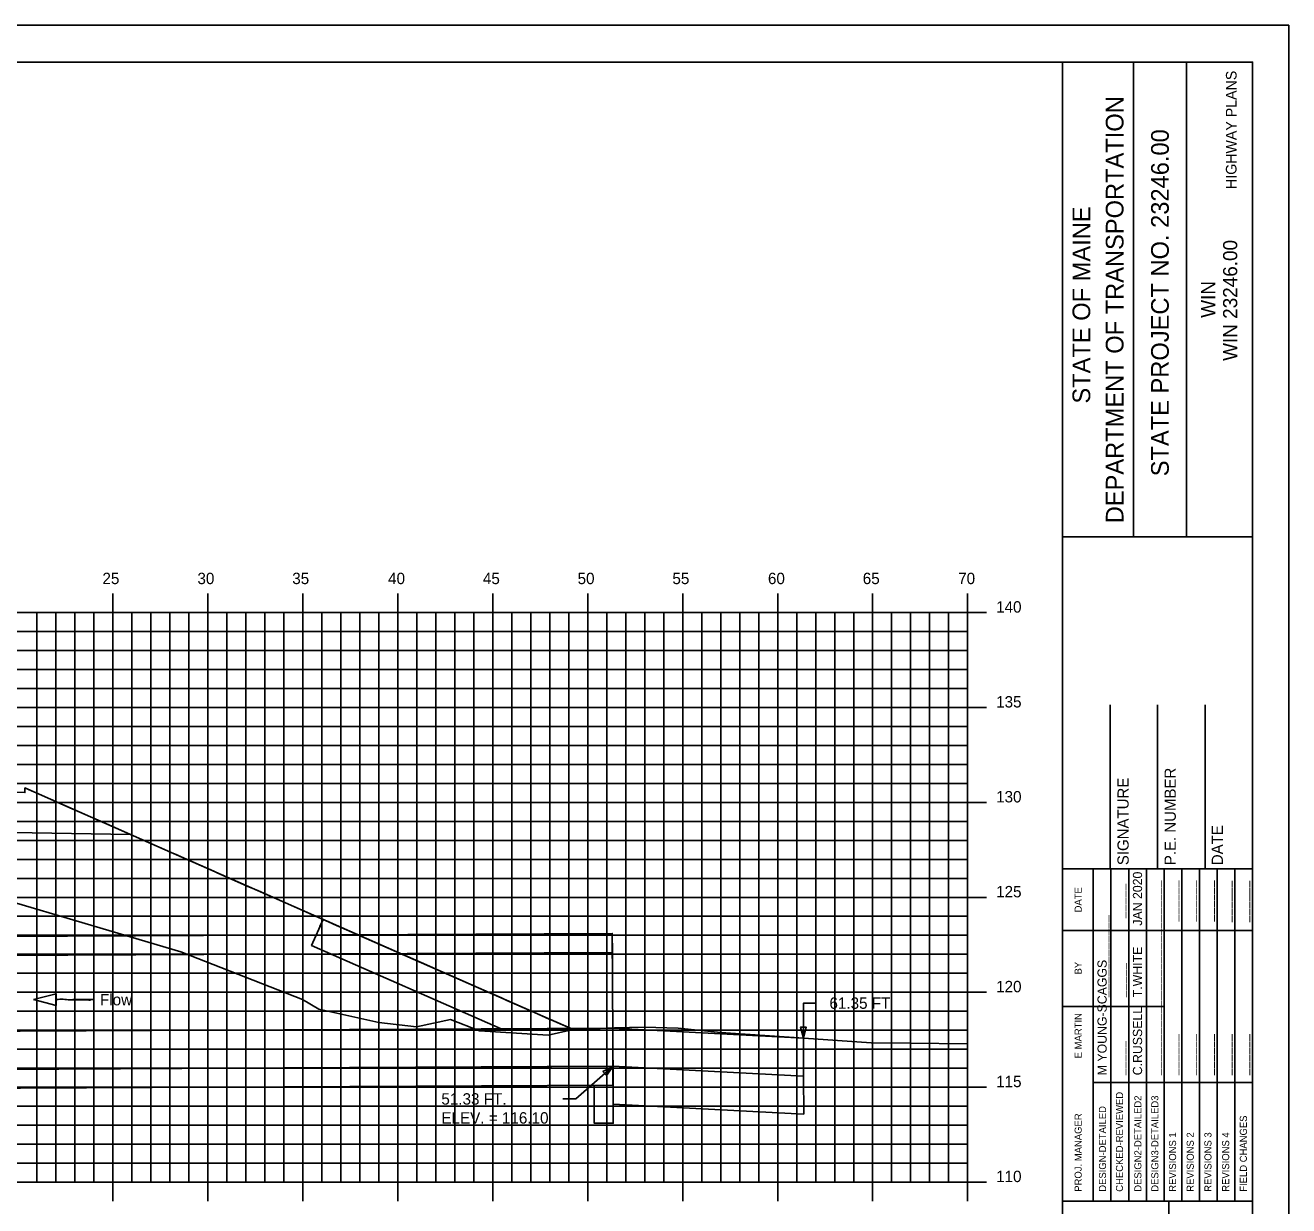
# Model space of a CAD drawing. Extents: x 1145859 to 1146029, y 608981 to 609091.
# Drawn here: x 1145962.8 to 1146029.3, y 609029.1 to 609091.3 of the extents above; entities that cross this region are included whole.
import ezdxf

# ---------------------------------------------------------------- set-up
doc = ezdxf.new("R2010")
doc.units = 0
for name, color, linetype in [('BORDER', 7, 'Continuous'), ('D_Drainage_Culvert', 7, 'Continuous'), ('D_Roadway_SlopeLines', 7, 'Continuous'), ('D_Roadway_SubGrade', 7, 'Continuous'), ('D_Text_Standard', 7, 'Continuous'), ('H_V ANNOTATION', 7, 'Continuous'), ('HIGHWAY_TITLE', 7, 'Continuous'), ('MAJOR', 7, 'Continuous'), ('MINOR', 7, 'Continuous'), ('PATTERNING', 7, 'Continuous'), ('PLOT BOUNDARY', 7, 'Continuous'), ('S_Roadway_Centerline', 7, 'Continuous'), ('WATER_DAM', 7, 'Continuous')]:
    doc.layers.add(name, color=color, linetype=linetype)

msp = doc.modelspace()

# ---------------------------------------------------------------- linework, layer by layer
msp.add_lwpolyline([(1145962.768, 609051.1), (1145963.118, 609050.946), (1145963.237, 609050.893), (1145963.479, 609050.786), (1145965.131, 609050.057), (1145965.943, 609049.698), (1145967.025, 609049.221), (1145968.331, 609048.645), (1145968.918, 609048.386), (1145968.972, 609048.362), (1145968.994, 609048.352), (1145969.706, 609048.038), (1145970.593, 609047.647), (1145970.812, 609047.55), (1145970.835, 609047.54), (1145972.706, 609046.715), (1145972.929, 609046.616), (1145974.599, 609045.879), (1145975.022, 609045.693), (1145976.493, 609045.044), (1145977.707, 609044.509), (1145978.387, 609044.209), (1145978.76, 609044.044), (1145979.019, 609043.93), (1145979.704, 609043.628), (1145980.28, 609043.374), (1145981.174, 609042.98), (1145982.174, 609042.539), (1145982.909, 609042.215), (1145984.068, 609041.704), (1145984.65, 609041.447), (1145985.962, 609040.869), (1145986.395, 609040.678), (1145987.855, 609040.035), (1145988.142, 609039.908), (1145989.749, 609039.2), (1145989.798, 609039.178), (1145990.37, 609038.926), (1145990.436, 609038.897), (1145991.643, 609038.366), (1145991.643, 609038.365), (1145991.651, 609038.362)])
at = {"layer": 'BORDER'}
for p, q in [((1146017.402, 608984.335), (1146017.402, 609089.335)), ((1146021.13, 609064.332), (1146021.13, 609089.332)), ((1146023.925, 609064.332), (1146023.925, 609089.332)), ((1146017.403, 609064.329), (1146027.402, 609064.329)), ((1146019.902, 609046.838), (1146019.902, 609055.485)), ((1146022.402, 609046.838), (1146022.402, 609055.485)), ((1146024.902, 609046.838), (1146024.902, 609055.485)), ((1146017.402, 609046.838), (1146027.402, 609046.838)), ((1146017.402, 609029.338), (1146027.402, 609029.338)), ((1146022.993, 608994.338), (1146022.993, 609029.338))]:
    msp.add_line(p, q, dxfattribs=at)
msp.add_lwpolyline([(1145867.402, 608984.335), (1146027.402, 608984.335), (1146027.402, 609089.335), (1145867.402, 609089.335)], close=True, dxfattribs=at)
for points in [[(1146019.017, 609043.588), (1146019.017, 609046.838)], [(1146019.949, 609029.341), (1146019.949, 609046.838)], [(1146020.881, 609046.838), (1146020.881, 609029.341)], [(1146021.813, 609029.341), (1146021.813, 609046.838)], [(1146022.744, 609029.341), (1146022.744, 609046.838)], [(1146023.676, 609029.341), (1146023.676, 609046.838)], [(1146024.608, 609029.341), (1146024.608, 609046.838)], [(1146025.539, 609029.341), (1146025.539, 609046.838)], [(1146026.471, 609029.341), (1146026.471, 609046.838)], [(1146019.018, 609029.341), (1146019.018, 609046.132)], [(1146017.402, 609043.588), (1146027.402, 609043.588)], [(1146017.402, 609039.588), (1146019.018, 609039.588)], [(1146019.017, 609039.588), (1146022.743, 609039.588)], [(1146019.017, 609035.588), (1146027.402, 609035.588)]]:
    msp.add_lwpolyline(points, dxfattribs=at)
at = {"layer": 'D_Drainage_Culvert'}
for points in [[(1145889.737, 609034.915), (1145993.735, 609035.435), (1145993.695, 609043.435), (1145889.697, 609042.915)], [(1145889.732, 609035.915), (1145993.73, 609036.435), (1145993.7, 609042.435), (1145889.702, 609041.915)], [(1145993.735, 609035.435), (1145992.735, 609035.43), (1145992.745, 609033.43), (1145993.745, 609033.435)]]:
    msp.add_lwpolyline(points, close=True, dxfattribs=at)
at = {"layer": 'D_Roadway_SlopeLines'}
for points in [[(1145968.331, 609048.645), (1145970.594, 609047.647)], [(1145970.594, 609047.647), (1145991.511, 609038.424)]]:
    msp.add_lwpolyline(points, dxfattribs=at)
at = {"layer": 'D_Roadway_SubGrade'}
msp.add_lwpolyline([(1145954.848, 609050.962), (1145954.848, 609051.129), (1145962.768, 609050.852), (1145962.768, 609051.102), (1145962.768, 609051.102), (1145968.331, 609048.645), (1145954.848, 609048.879)], close=True, dxfattribs=at)
at = {"layer": 'D_Text_Standard'}
for points in [[(1146003.752, 609037.912), (1146003.766, 609039.762), (1146004.446, 609039.762)], [(1145993.732, 609036.435), (1145991.777, 609034.716), (1145991.097, 609034.716)]]:
    msp.add_lwpolyline(points, dxfattribs=at)
for points in [[(1146003.752, 609037.912), (1146003.611, 609038.496), (1146003.902, 609038.493)], [(1145993.732, 609036.435), (1145993.391, 609035.941), (1145993.198, 609036.16)]]:
    msp.add_lwpolyline(points, close=True, dxfattribs=at)
at = {"layer": 'MAJOR'}
for p, q in [((1145967.402, 609061.337), (1145967.402, 609060.335)), ((1145972.402, 609061.337), (1145972.402, 609060.335)), ((1145977.402, 609061.337), (1145977.402, 609060.335)), ((1145982.402, 609061.337), (1145982.402, 609060.335)), ((1145987.402, 609061.337), (1145987.402, 609060.335)), ((1145992.402, 609061.337), (1145992.402, 609060.335)), ((1145997.402, 609061.337), (1145997.402, 609060.335)), ((1146002.402, 609061.337), (1146002.402, 609060.335)), ((1146007.402, 609061.337), (1146007.402, 609060.335)), ((1146012.402, 609061.337), (1146012.402, 609060.335)), ((1145872.402, 609060.335), (1146012.402, 609060.335)), ((1145872.402, 609060.335), (1146012.402, 609060.335)), ((1145967.402, 609030.335), (1145967.402, 609060.335)), ((1145972.402, 609030.335), (1145972.402, 609060.335)), ((1145977.402, 609030.335), (1145977.402, 609060.335)), ((1145982.402, 609030.335), (1145982.402, 609060.335)), ((1145987.402, 609030.335), (1145987.402, 609060.335)), ((1145992.402, 609030.335), (1145992.402, 609060.335)), ((1145997.402, 609030.335), (1145997.402, 609060.335)), ((1146002.402, 609030.335), (1146002.402, 609060.335)), ((1146007.402, 609030.335), (1146007.402, 609060.335)), ((1146013.404, 609060.335), (1146011.4, 609060.335)), ((1146012.402, 609030.335), (1146012.402, 609060.335)), ((1146012.402, 609030.335), (1146012.402, 609060.335)), ((1145872.402, 609055.335), (1146012.402, 609055.335)), ((1146013.404, 609055.335), (1146011.4, 609055.335)), ((1145872.402, 609050.335), (1146012.402, 609050.335)), ((1146013.404, 609050.335), (1146011.4, 609050.335)), ((1145872.402, 609045.335), (1146012.402, 609045.335)), ((1146013.404, 609045.335), (1146011.4, 609045.335)), ((1145872.402, 609040.335), (1146012.402, 609040.335)), ((1146013.404, 609040.335), (1146011.4, 609040.335)), ((1145872.402, 609035.335), (1146012.402, 609035.335)), ((1146013.404, 609035.335), (1146011.4, 609035.335)), ((1145872.402, 609030.335), (1146012.402, 609030.335)), ((1145872.402, 609030.335), (1146012.402, 609030.335)), ((1145967.402, 609029.333), (1145967.402, 609030.335)), ((1145972.402, 609029.333), (1145972.402, 609030.335)), ((1145977.402, 609029.333), (1145977.402, 609030.335)), ((1145982.402, 609029.333), (1145982.402, 609030.335)), ((1145987.402, 609029.333), (1145987.402, 609030.335)), ((1145992.402, 609029.333), (1145992.402, 609030.335)), ((1145997.402, 609029.333), (1145997.402, 609030.335)), ((1146002.402, 609029.333), (1146002.402, 609030.335)), ((1146007.402, 609029.333), (1146007.402, 609030.335)), ((1146013.404, 609030.335), (1146011.4, 609030.335)), ((1146012.402, 609029.333), (1146012.402, 609030.335))]:
    msp.add_line(p, q, dxfattribs=at)
at = {"layer": 'MINOR'}
for p, q in [((1145963.402, 609030.335), (1145963.402, 609060.335)), ((1145964.402, 609030.335), (1145964.402, 609060.335)), ((1145965.402, 609030.335), (1145965.402, 609060.335)), ((1145966.402, 609030.335), (1145966.402, 609060.335)), ((1145968.402, 609030.335), (1145968.402, 609060.335)), ((1145969.402, 609030.335), (1145969.402, 609060.335)), ((1145970.402, 609030.335), (1145970.402, 609060.335)), ((1145971.402, 609030.335), (1145971.402, 609060.335)), ((1145973.402, 609030.335), (1145973.402, 609060.335)), ((1145974.402, 609030.335), (1145974.402, 609060.335)), ((1145975.402, 609030.335), (1145975.402, 609060.335)), ((1145976.402, 609030.335), (1145976.402, 609060.335)), ((1145978.402, 609030.335), (1145978.402, 609060.335)), ((1145979.402, 609030.335), (1145979.402, 609060.335)), ((1145980.402, 609030.335), (1145980.402, 609060.335)), ((1145981.402, 609030.335), (1145981.402, 609060.335)), ((1145983.402, 609030.335), (1145983.402, 609060.335)), ((1145984.402, 609030.335), (1145984.402, 609060.335)), ((1145985.402, 609030.335), (1145985.402, 609060.335)), ((1145986.402, 609030.335), (1145986.402, 609060.335)), ((1145988.402, 609030.335), (1145988.402, 609060.335)), ((1145989.402, 609030.335), (1145989.402, 609060.335)), ((1145990.402, 609030.335), (1145990.402, 609060.335)), ((1145991.402, 609030.335), (1145991.402, 609060.335)), ((1145993.402, 609030.335), (1145993.402, 609060.335)), ((1145994.402, 609030.335), (1145994.402, 609060.335)), ((1145995.402, 609030.335), (1145995.402, 609060.335)), ((1145996.402, 609030.335), (1145996.402, 609060.335)), ((1145998.402, 609030.335), (1145998.402, 609060.335)), ((1145999.402, 609030.335), (1145999.402, 609060.335)), ((1146000.402, 609030.335), (1146000.402, 609060.335)), ((1146001.402, 609030.335), (1146001.402, 609060.335)), ((1146003.402, 609030.335), (1146003.402, 609060.335)), ((1146004.402, 609030.335), (1146004.402, 609060.335)), ((1146005.402, 609030.335), (1146005.402, 609060.335)), ((1146006.402, 609030.335), (1146006.402, 609060.335)), ((1146008.402, 609030.335), (1146008.402, 609060.335)), ((1146009.402, 609030.335), (1146009.402, 609060.335)), ((1146010.402, 609030.335), (1146010.402, 609060.335)), ((1146011.402, 609030.335), (1146011.402, 609060.335)), ((1145872.402, 609059.335), (1146012.402, 609059.335)), ((1146012.402, 609059.335), (1146011.4, 609059.335)), ((1145872.402, 609058.335), (1146012.402, 609058.335)), ((1146012.402, 609058.335), (1146011.4, 609058.335)), ((1145872.402, 609057.335), (1146012.402, 609057.335)), ((1146012.402, 609057.335), (1146011.4, 609057.335)), ((1145872.402, 609056.335), (1146012.402, 609056.335)), ((1146012.402, 609056.335), (1146011.4, 609056.335)), ((1145872.402, 609054.335), (1146012.402, 609054.335)), ((1146012.402, 609054.335), (1146011.4, 609054.335)), ((1145872.402, 609053.335), (1146012.402, 609053.335)), ((1146012.402, 609053.335), (1146011.4, 609053.335)), ((1145872.402, 609052.335), (1146012.402, 609052.335)), ((1146012.402, 609052.335), (1146011.4, 609052.335)), ((1145872.402, 609051.335), (1146012.402, 609051.335)), ((1146012.402, 609051.335), (1146011.4, 609051.335)), ((1145872.402, 609049.335), (1146012.402, 609049.335)), ((1146012.402, 609049.335), (1146011.4, 609049.335)), ((1145872.402, 609048.335), (1146012.402, 609048.335)), ((1146012.402, 609048.335), (1146011.4, 609048.335)), ((1145872.402, 609047.335), (1146012.402, 609047.335)), ((1146012.402, 609047.335), (1146011.4, 609047.335)), ((1145872.402, 609046.335), (1146012.402, 609046.335)), ((1146012.402, 609046.335), (1146011.4, 609046.335)), ((1145872.402, 609044.335), (1146012.402, 609044.335)), ((1146012.402, 609044.335), (1146011.4, 609044.335)), ((1145872.402, 609043.335), (1146012.402, 609043.335)), ((1146012.402, 609043.335), (1146011.4, 609043.335)), ((1145872.402, 609042.335), (1146012.402, 609042.335)), ((1146012.402, 609042.335), (1146011.4, 609042.335)), ((1145872.402, 609041.335), (1146012.402, 609041.335)), ((1146012.402, 609041.335), (1146011.4, 609041.335)), ((1145872.402, 609039.335), (1146012.402, 609039.335)), ((1146012.402, 609039.335), (1146011.4, 609039.335)), ((1145872.402, 609038.335), (1146012.402, 609038.335)), ((1146012.402, 609038.335), (1146011.4, 609038.335)), ((1145872.402, 609037.335), (1146012.402, 609037.335)), ((1146012.402, 609037.335), (1146011.4, 609037.335)), ((1145872.402, 609036.335), (1146012.402, 609036.335)), ((1146012.402, 609036.335), (1146011.4, 609036.335)), ((1145872.402, 609034.335), (1146012.402, 609034.335)), ((1146012.402, 609034.335), (1146011.4, 609034.335)), ((1145872.402, 609033.335), (1146012.402, 609033.335)), ((1146012.402, 609033.335), (1146011.4, 609033.335)), ((1145872.402, 609032.335), (1146012.402, 609032.335)), ((1146012.402, 609032.335), (1146011.4, 609032.335)), ((1145872.402, 609031.335), (1146012.402, 609031.335)), ((1146012.402, 609031.335), (1146011.4, 609031.335))]:
    msp.add_line(p, q, dxfattribs=at)
at = {"layer": 'PATTERNING'}
for p, q in [((1145993.7, 609042.435), (1145993.695, 609043.435)), ((1145889.702, 609041.915), (1145993.7, 609042.435)), ((1145991.511, 609038.424), (1145991.511, 609038.424)), ((1145993.73, 609036.435), (1145889.732, 609035.915)), ((1145889.732, 609035.915), (1145993.732, 609036.435))]:
    msp.add_line(p, q, dxfattribs=at)
for points in [[(1145991.511, 609038.424), (1145980.298, 609043.368), (1145978.468, 609044.175), (1145977.863, 609042.802), (1145987.837, 609038.406), (1145991.511, 609038.424)], [(1145980.298, 609043.368), (1145978.468, 609044.175), (1145978.3, 609043.795)], [(1145993.695, 609043.435), (1145889.697, 609042.915), (1145889.702, 609041.915)], [(1145889.737, 609034.915), (1145993.735, 609035.435), (1145993.73, 609036.435)]]:
    msp.add_lwpolyline(points, dxfattribs=at)
for points in [[(1145889.732, 609035.915), (1145889.722, 609037.915), (1145993.72, 609038.435), (1145993.73, 609036.435)], [(1145993.72, 609038.435), (1146003.752, 609037.912), (1146003.761, 609035.912), (1145993.73, 609036.435)], [(1145993.73, 609036.435), (1146003.761, 609035.912), (1146003.771, 609033.913), (1145993.74, 609034.435)]]:
    msp.add_lwpolyline(points, close=True, dxfattribs=at)
at = {"layer": 'PLOT BOUNDARY'}
msp.add_lwpolyline([(1145859.308, 608981.276), (1146029.308, 608981.276), (1146029.308, 609091.276), (1145859.308, 609091.276)], close=True, dxfattribs=at)
at = {"layer": 'S_Roadway_Centerline'}
msp.add_lwpolyline([(1145956.617, 609046.711), (1145970.97, 609042.471), (1145977.379, 609039.948), (1145978.241, 609039.442), (1145981.393, 609038.75), (1145983.393, 609038.522), (1145985.169, 609038.895), (1145986.704, 609038.311), (1145990.311, 609038.078), (1145991.564, 609038.358), (1145993.811, 609038.455), (1145995.381, 609038.499), (1145997.157, 609038.441), (1145999.407, 609038.212), (1146003.773, 609037.911), (1146007.319, 609037.668), (1146009.397, 609037.646), (1146012.402, 609037.617)], dxfattribs=at)
at = {"layer": 'WATER_DAM'}
msp.add_lwpolyline([(1145963.218, 609039.945), (1145964.418, 609040.245), (1145964.418, 609039.645)], close=True, dxfattribs=at)
msp.add_open_spline([(1145964.418, 609039.945), (1145964.668, 609039.995), (1145965.168, 609039.895), (1145965.668, 609039.995), (1145966.168, 609039.895), (1145966.418, 609039.945), (1145964.418, 609039.945), (1145966.418, 609039.945)], degree=3, dxfattribs=at)

# ---------------------------------------------------------------- texts
at = {"layer": 'BORDER'}
for s, height, p in [('DEPARTMENT OF TRANSPORTATION', 0.93176, (1146020.609, 609065.041)), ('STATE PROJECT NO. 23246.00', 0.93176, (1146022.994, 609067.517)), ('STATE OF MAINE', 0.93176, (1146018.857, 609071.347)), ('WIN 23246.00', 0.74527, (1146026.597, 609073.596)), ('WIN', 0.7453, (1146025.439, 609075.865)), ('P.E. NUMBER', 0.59055, (1146023.363, 609047.03)), ('SIGNATURE', 0.5906, (1146020.882, 609047.03)), ('DATE', 0.5906, (1146025.843, 609047.03)), ('JAN 2020', 0.4845, (1146021.588, 609043.843)), ('DATE', 0.3714, (1146018.406, 609044.544)), ('_____', 0.4845, (1146020.619, 609044.243)), ('______', 0.4845, (1146022.483, 609044.063)), ('______', 0.4845, (1146023.414, 609044.065)), ('______', 0.4845, (1146024.346, 609044.067)), ('______', 0.4845, (1146025.278, 609044.067)), ('______', 0.4845, (1146026.209, 609044.036)), ('______', 0.4845, (1146027.141, 609044.036)), ('____________', 0.48455, (1146019.725, 609040.073)), ('____________', 0.48455, (1146022.483, 609040.073)), ('T.WHITE', 0.4845, (1146021.588, 609040.073)), ('BY', 0.3714, (1146018.406, 609041.273)), ('M YOUNG-SCAGGS', 0.48455, (1146019.725, 609035.961)), ('_____', 0.4845, (1146020.656, 609040.073)), ('____________', 0.48455, (1146022.483, 609035.961)), ('E MARTIN', 0.3727, (1146018.406, 609036.855)), ('C.RUSSELL', 0.4845, (1146021.588, 609035.961)), ('_____', 0.4845, (1146020.619, 609035.961)), ('______', 0.4845, (1146023.414, 609035.961)), ('______', 0.4845, (1146024.346, 609035.961)), ('______', 0.4845, (1146025.278, 609035.961)), ('______', 0.4845, (1146026.209, 609035.961)), ('______', 0.4845, (1146027.141, 609035.961)), ('CHECKED-REVIEWED', 0.37275, (1146020.583, 609029.826)), ('DESIGN-DETAILED', 0.37275, (1146019.688, 609029.826)), ('DESIGN2-DETAILED2', 0.37275, (1146021.552, 609029.826)), ('DESIGN3-DETAILED3', 0.37275, (1146022.446, 609029.826)), ('PROJ. MANAGER', 0.37275, (1146018.406, 609029.826)), ('FIELD CHANGES', 0.37275, (1146027.105, 609029.826)), ('REVISIONS 1', 0.37275, (1146023.378, 609029.826)), ('REVISIONS 2', 0.37275, (1146024.31, 609029.826)), ('REVISIONS 3', 0.37275, (1146025.241, 609029.826)), ('REVISIONS 4', 0.37275, (1146026.173, 609029.826))]:
    msp.add_text(s, height=height, rotation=90, dxfattribs=at).set_placement(p)
at = {"layer": 'D_Text_Standard'}
for s, p in [('61.35 FT', (1146005.126, 609039.462)), ('51.33 FT.', (1145984.693, 609034.416)), ('ELEV. = 116.10', (1145984.693, 609033.416))]:
    msp.add_text(s, height=0.6, dxfattribs=at).set_placement(p)
at = {"layer": 'H_V ANNOTATION'}
for s, p in [('25', (1145966.848, 609061.835)), ('30', (1145971.85, 609061.835)), ('35', (1145976.842, 609061.835)), ('40', (1145981.888, 609061.835)), ('45', (1145986.88, 609061.835)), ('50', (1145991.866, 609061.835)), ('55', (1145996.858, 609061.835)), ('60', (1146001.888, 609061.835)), ('65', (1146006.88, 609061.835)), ('70', (1146011.904, 609061.835)), ('140', (1146013.902, 609060.335)), ('135', (1146013.902, 609055.335)), ('130', (1146013.902, 609050.335)), ('125', (1146013.902, 609045.335)), ('120', (1146013.902, 609040.335)), ('115', (1146013.902, 609035.335)), ('110', (1146013.902, 609030.335))]:
    msp.add_text(s, height=0.6, dxfattribs=at).set_placement(p)
at = {"layer": 'HIGHWAY_TITLE'}
msp.add_text('HIGHWAY PLANS', height=0.55901, rotation=90, dxfattribs=at).set_placement((1146026.56, 609082.65))
at = {"layer": 'WATER_DAM'}
msp.add_text('Flow', height=0.6, dxfattribs=at).set_placement((1145966.718, 609039.645))

doc.saveas('drawing.dxf')
